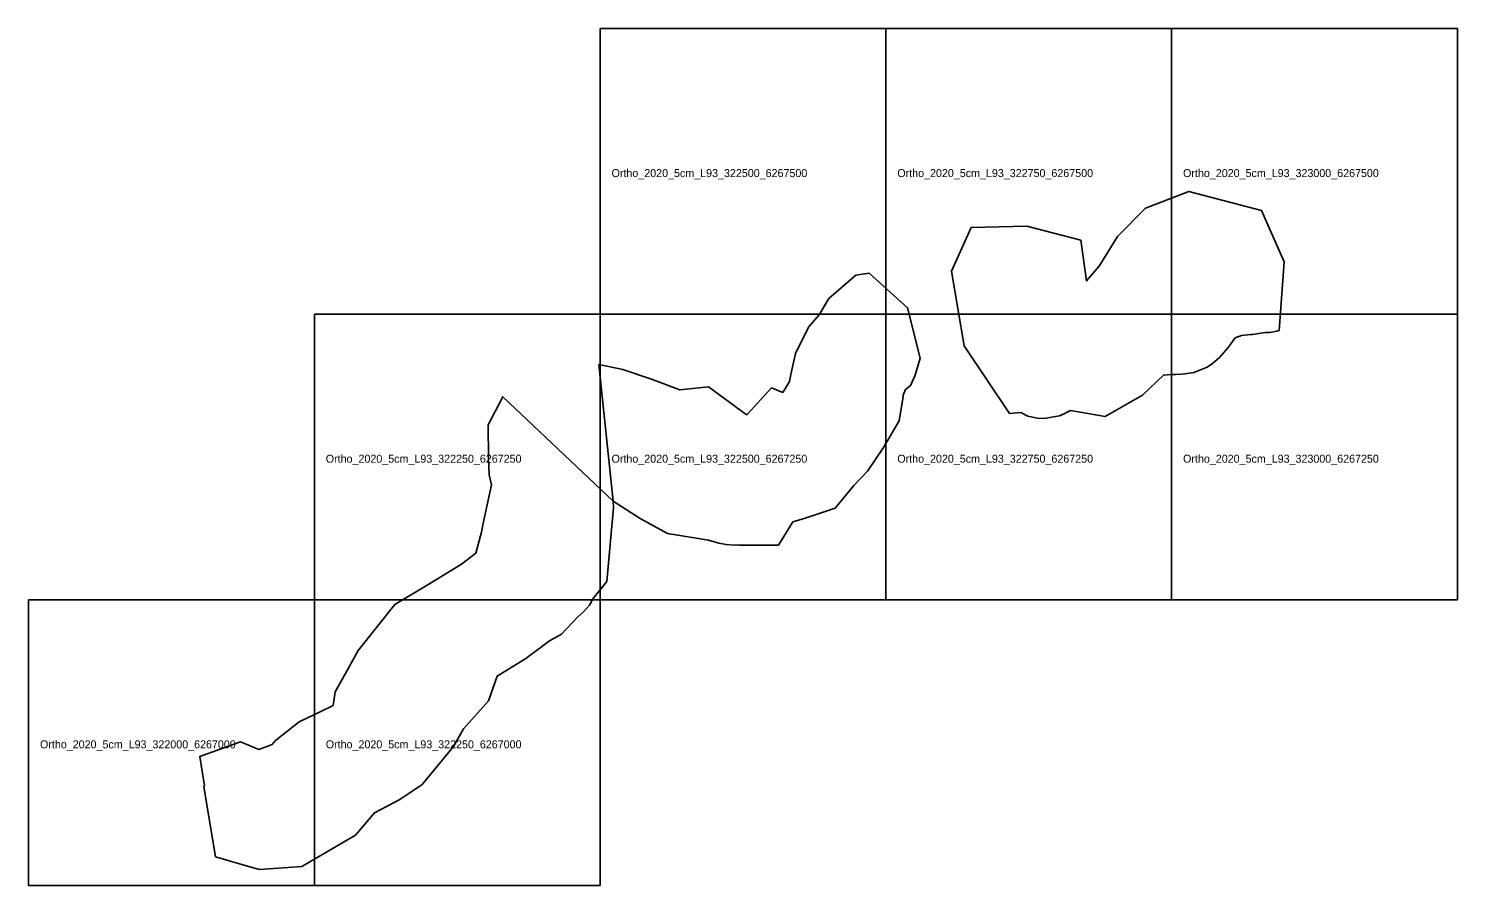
# Model space of a CAD drawing. Extents: x 322000 to 326000, y 6266750 to 6269250.
# Drawn here: x 322000 to 323250, y 6266750 to 6267500 of the extents above; entities that cross this region are included whole.
import ezdxf

# ---------------------------------------------------------------- set-up
doc = ezdxf.new("R2010")
doc.units = 0
for name, color, linetype in [('Ortho_footprint', 7, 'Continuous'), ('Ortho_name', 7, 'Continuous'), ('Perim', 7, 'Continuous')]:
    doc.layers.add(name, color=color, linetype=linetype)

msp = doc.modelspace()

# ---------------------------------------------------------------- linework, layer by layer
at = {"layer": 'Ortho_footprint'}
for points in [[(322500, 6267500), (322750, 6267500), (322750, 6267250), (322500, 6267250)], [(322750, 6267500), (323000, 6267500), (323000, 6267250), (322750, 6267250)], [(323000, 6267500), (323250, 6267500), (323250, 6267250), (323000, 6267250)], [(322250, 6267250), (322500, 6267250), (322500, 6267000), (322250, 6267000)], [(322500, 6267250), (322750, 6267250), (322750, 6267000), (322500, 6267000)], [(322750, 6267250), (323000, 6267250), (323000, 6267000), (322750, 6267000)], [(323000, 6267250), (323250, 6267250), (323250, 6267000), (323000, 6267000)], [(322000, 6267000), (322250, 6267000), (322250, 6266750), (322000, 6266750)], [(322250, 6267000), (322500, 6267000), (322500, 6266750), (322250, 6266750)]]:
    msp.add_lwpolyline(points, close=True, dxfattribs=at)
at = {"layer": 'Perim'}
for points in [[(323094.2, 6267235.7), (323092, 6267235.1), (323085.9, 6267234.1), (323081.8, 6267233.9), (323070.7, 6267232.3), (323069.4, 6267232.1), (323061.2, 6267231.3), (323055.6, 6267229.2), (323055.2, 6267228.9), (323051.3, 6267223.3), (323049.4, 6267220.9), (323041.8, 6267212.1), (323035.7, 6267206.7), (323031.2, 6267203.7), (323019.3, 6267199), (323011.7, 6267197.8), (323008, 6267197.4), (323003.6, 6267197.3), (322999.4, 6267197.1), (322992.8, 6267196.7), (322974.6, 6267179), (322941.9, 6267160.5), (322911.4, 6267165.7), (322908.5, 6267164.1), (322906.6, 6267163.2), (322901.8, 6267161.1), (322888.1, 6267158.7), (322882.6, 6267159), (322874.1, 6267160.7), (322868.2, 6267163.9), (322858, 6267163.1), (322818.4, 6267222.2), (322807.3, 6267287.8), (322824.6, 6267325.9), (322873.4, 6267326.9), (322920.5, 6267314.8), (322925.5, 6267279.1), (322936.7, 6267291.9), (322952.6, 6267318.1), (322977.1, 6267342.7), (323015, 6267357.5), (323078.7, 6267340.9), (323098.3, 6267295.9)], [(322735.4, 6267285.9), (322768.9, 6267255.7), (322780, 6267211.6), (322775.6, 6267196.7), (322771.5, 6267187.5), (322767.2, 6267184.1), (322765.2, 6267179.1), (322765, 6267178), (322761.6, 6267156.6), (322747.9, 6267133.2), (322734, 6267112.7), (322722, 6267100.2), (322705.6, 6267080.3), (322678.4, 6267071.2), (322668.7, 6267068.2), (322656, 6267047.8), (322621.5, 6267047.7), (322619.5, 6267048), (322617.5, 6267047.9), (322610.2, 6267048.4), (322604, 6267049.5), (322594.9, 6267052.1), (322559, 6267057.9), (322535.1, 6267071.3), (322511.4, 6267086.2), (322498.9, 6267205.9), (322519.9, 6267201.5), (322544.9, 6267193.2), (322569.7, 6267183.9), (322594.9, 6267186.4), (322627.8, 6267162.1), (322628.7, 6267162.1), (322650, 6267185.5), (322659.8, 6267181.6), (322663.1, 6267186.6), (322665.7, 6267191.1), (322666.8, 6267197.2), (322671, 6267215.5), (322682.4, 6267238.5), (322691.7, 6267249.4), (322700.1, 6267263.6), (322723.8, 6267284.1)], [(322511.4, 6267086.2), (322511.7, 6267080.5), (322505.8, 6267016.1), (322493.7, 6267001), (322490.8, 6266995.3), (322485.6, 6266989.5), (322480.2, 6266984.9), (322466.2, 6266969.8), (322455.8, 6266964.1), (322435.1, 6266948.6), (322409.9, 6266933.1), (322402.3, 6266911.6), (322380.4, 6266887), (322371.6, 6266871.5), (322344.2, 6266838.3), (322324.9, 6266825.1), (322302.6, 6266813.6), (322286.1, 6266794.1), (322239.1, 6266766.7), (322202, 6266764), (322193.5, 6266766.4), (322163.6, 6266775.1), (322153.2, 6266836.6), (322153.8, 6266837.3), (322149.7, 6266863), (322185.5, 6266875.7), (322201.3, 6266869), (322213, 6266873.4), (322216, 6266876.9), (322236.8, 6266893.2), (322255.8, 6266902.1), (322266.5, 6266907.6), (322268.2, 6266919.4), (322277.4, 6266935.6), (322288.3, 6266955.6), (322320.3, 6266996), (322348.7, 6267012.8), (322378.6, 6267031.3), (322391.2, 6267040.8), (322396.1, 6267059.3), (322397.5, 6267065.6), (322404.9, 6267100.6), (322403, 6267109.5), (322402.3, 6267124.1), (322402.1, 6267153.3), (322414.8, 6267177.7)]]:
    msp.add_lwpolyline(points, close=True, dxfattribs=at)

# ---------------------------------------------------------------- texts
at = {"layer": 'Ortho_name'}
for s, p in [('Ortho_2020_5cm_L93_322500_6267500', (322510, 6267370)), ('Ortho_2020_5cm_L93_322750_6267500', (322760, 6267370)), ('Ortho_2020_5cm_L93_323000_6267500', (323010, 6267370)), ('Ortho_2020_5cm_L93_322250_6267250', (322260, 6267120)), ('Ortho_2020_5cm_L93_322500_6267250', (322510, 6267120)), ('Ortho_2020_5cm_L93_322750_6267250', (322760, 6267120)), ('Ortho_2020_5cm_L93_323000_6267250', (323010, 6267120)), ('Ortho_2020_5cm_L93_322000_6267000', (322010, 6266870)), ('Ortho_2020_5cm_L93_322250_6267000', (322260, 6266870))]:
    msp.add_text(s, height=7, dxfattribs=at).set_placement(p)

doc.saveas('drawing.dxf')
